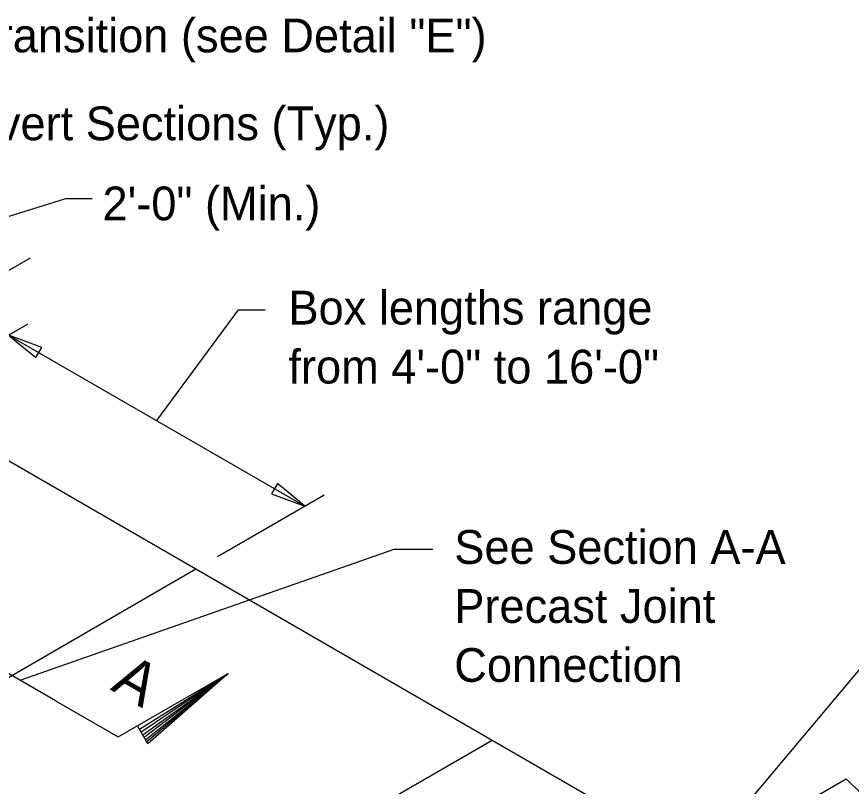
# Model space of a CAD drawing. Extents: x 10050 to 10414, y 76434 to 76519.
# Drawn here: x 10236.85 to 10251.8, y 76497.13 to 76510.9 of the extents above; entities that cross this region are included whole.
import ezdxf

# ---------------------------------------------------------------- set-up
doc = ezdxf.new("R2010")
doc.units = 0
for name, color, linetype in [('Patterning', 7, 'Continuous'), ('PlotBorder_dp', 7, 'Continuous'), ('SheetLines_dp', 7, 'Continuous')]:
    doc.layers.add(name, color=color, linetype=linetype)

msp = doc.modelspace()

# ---------------------------------------------------------------- linework, layer by layer
at = {"layer": 'Patterning'}
for p, q in [((10235.737, 76507.024), (10237.732, 76507.646)), ((10237.732, 76507.646), (10238.208, 76507.646)), ((10235.899, 76505.893), (10237.103, 76506.587)), ((10246.754, 76493.028), (10257.859, 76506.261)), ((10239.361, 76503.672), (10240.826, 76505.657)), ((10240.826, 76505.657), (10241.302, 76505.657)), ((10235.077, 76504.26), (10237.059, 76505.404)), ((10236.709, 76505.203), (10242.013, 76502.141)), ((10240.452, 76501.24), (10242.362, 76502.343)), ((10237.56, 76498.652), (10235.969, 76499.57)), ((10238.673, 76498.01), (10240.641, 76499.146)), ((10239.052, 76498.148), (10240.641, 76499.146)), ((10240.641, 76499.146), (10239.082, 76498.096)), ((10239.11, 76498.048), (10240.641, 76499.146)), ((10240.641, 76499.146), (10239.137, 76498.001)), ((10239.162, 76497.957), (10240.641, 76499.146)), ((10240.641, 76499.146), (10239.182, 76497.923)), ((10240.641, 76499.146), (10239.205, 76497.884)), ((10237.56, 76498.652), (10238.673, 76498.01)), ((10239.205, 76497.884), (10239.017, 76498.208))]:
    msp.add_line(p, q, dxfattribs=at)
for points in [[(10236.71, 76505.203), (10237.198, 76504.799), (10237.303, 76504.982)], [(10242.013, 76502.141), (10241.525, 76502.545), (10241.419, 76502.362)]]:
    msp.add_lwpolyline(points, close=True, dxfattribs=at)
msp.add_lwpolyline([(10236.917, 76499.023), (10243.616, 76501.373), (10244.305, 76501.373)], dxfattribs=at)
at = {"layer": 'PlotBorder_dp'}
for p, q in [((10234.761, 76504.078), (10240.064, 76501.016)), ((10233.524, 76497.24), (10240.064, 76501.016)), ((10240.064, 76501.016), (10245.368, 76497.954)), ((10238.827, 76494.178), (10245.368, 76497.954)), ((10245.368, 76497.954), (10249.138, 76495.778)), ((10236.706, 76488.6), (10251.709, 76497.262)), ((10251.709, 76497.262), (10252.426, 76496.554))]:
    msp.add_line(p, q, dxfattribs=at)

# ---------------------------------------------------------------- texts
at = {"layer": 'Patterning'}
for s, p in [('Box lengths range ', (10241.721, 76505.392)), ('from 4\'-0" to 16\'-0"', (10241.721, 76504.336)), ('See Section A-A', (10244.691, 76501.107)), ('Precast Joint', (10244.691, 76500.051)), ('Connection', (10244.691, 76498.995))]:
    msp.add_text(s, height=0.6048, dxfattribs=at).set_placement(p)
at = {"layer": 'SheetLines_dp'}
for s, p in [('C-I-P Exterior Wall/Slab Transition (see Detail "E")', (10227.257, 76510.265)), ('Precast Box Culvert Sections (Typ.)', (10230.719, 76508.691)), ('2\'-0" (Min.)', (10238.391, 76507.257))]:
    msp.add_text(s, height=0.6048, dxfattribs=at).set_placement(p)
msp.add_text('A', height=0.768, rotation=330, dxfattribs=at).set_placement((10238.516, 76498.861))

doc.saveas('drawing.dxf')
